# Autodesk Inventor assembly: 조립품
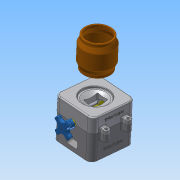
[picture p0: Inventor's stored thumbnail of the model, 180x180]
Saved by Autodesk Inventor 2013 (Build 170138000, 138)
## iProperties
Created: 2018-01
Part Number: 조립품
Document SubType Name: Assembly
Designer: Administrator
Author: Administrator
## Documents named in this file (7)
- C:\Users\Administrator\Desktop\480108V1031\조립품.iam
- C:\Users\Administrator\Desktop\480108V1031\본체.ipt
- C:\Users\Administrator\Desktop\480108V1031\핸들축.ipt
- C:\Users\Administrator\Desktop\480108V1031\핸들.ipt
- C:\Users\Administrator\Desktop\480108V1031\볼트 M3x12.ipt
- C:\Users\Administrator\Desktop\480108V1031\본체커버.ipt
- C:\Users\Administrator\Desktop\480108V1031\용기.ipt
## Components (2 placed, 2 different names)
1. 핸들축:1
2. 핸들:1
